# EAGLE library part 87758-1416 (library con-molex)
14 Pin - 2mm Dual Row Single Wafer, Vertical T/H HDR Source: http://www.molex.com/pdm_docs/sd/877580616_sd.pdf
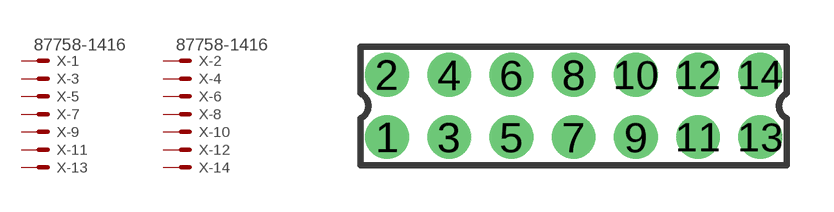
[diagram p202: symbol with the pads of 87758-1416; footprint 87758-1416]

Designator prefix X; gates -1=MV -2=MV -3=M -4=M -5=M -6=M -7=M -8=M -9=M -10=M -11=M -12=M -13=M -14=M

## 87758-1416 (MF: MOLEX; MPN: 87758-1416; OC_FARNELL: 7472358; OC_NEWARK: 59J1562)  [87758-1416]
1  -1:S  pas
2  -2:S  pas
3  -3:S  pas
4  -4:S  pas
5  -5:S  pas
6  -6:S  pas
7  -7:S  pas
8  -8:S  pas
9  -9:S  pas
10  -10:S  pas
11  -11:S  pas
12  -12:S  pas
13  -13:S  pas
14  -14:S  pas

## Footprint 87758-1416 (pad centres in mm)
14 Pin - 2mm Dual Row Single Wafer, Vertical T/H HDR Source: http://www.molex.com/pdm_docs/sd/877580616_sd.pdf
drill 0.9 pad 1.27 round: 1 -6,-1; 2 -6,1; 3 -4,-1; 4 -4,1; 5 -2,-1; 6 -2,1; 7 0,-1; 8 0,1; 9 2,-1; 10 2,1; 11 4,-1; 12 4,1; 13 6,-1; 14 6,1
